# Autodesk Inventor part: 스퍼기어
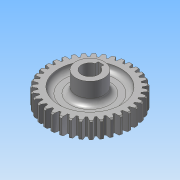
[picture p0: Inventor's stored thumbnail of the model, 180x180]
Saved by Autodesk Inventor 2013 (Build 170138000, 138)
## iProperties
Created: 2013-08
Part Number: 스퍼기어
Material: 강
Document SubType Name: Modeling
Designer: 한국산업디자인학원
Categories: <?xml version="1.0" encoding="UTF-16"?> <MemberInstance><Categories><FamilyTemplate><FamilyTemplateParameter ValueType="xs:double" Id="1" ObjectReferenceKey="da
Density: 1 g/cm^3
CustomPartVersion: 1
Author: 한국산업디자인학원
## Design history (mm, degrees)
sketch "Sketch1"
  geometry: C1 r 37 at (0, 0)
  constraints: 1 centre point
  dimensions: "d0" = 74 diameter of C1 (= da_da)
extrude "Extrusion1" new body sketch "Sketch1" distance "d1" = 15 (= da_b); taper "d2" = 0 deg
chamfer "모따기1" distance "d49" = 1; stored, may be unused: second distance "d50" = 2, angle "d51" = 45 deg
workplane "Work Plane2"
feature "피치 지름" dims "d4" = 10, "d5" = 0
workplane "Work Plane8"
workplane "Work Plane9"
feature "스퍼 기어" dims "da_b" = 15, "da_d" = 70, "da_aw" = 70, "da_da" = 74, "da_df" = 65, "da_dw" = 70, angle "da_beta" = 0 deg, "da_lefttooth" = 0, "da_righttooth" = 0
node "작업 평면11"
sketch "스케치3"
  geometry: L1 (-2.5, 7.071)-(-2.5, 9.8); L2 (-2.5, 9.8)-(2.5, 9.8); L3 (2.5, 9.8)-(2.5, 7.071); C1 r 12.5 at (0, 0); A1 r 7.5 centre (0, 0) between (-2.5, 7.071) and (2.5, 7.071); 1 further point
  constraints: 6 end point, 2 centre point, 2 coincident, 2 parallel, 2 point on circle, 1 perpendicular, 1 vertical
  dimensions: "d53" = 25 diameter of C1; "d55" = 15 diameter of A1; "d56" = 5 distance of L1.end L2.end; "d57" = 17.3 dimension on A1 L2
extrude "돌출2" join sketch "스케치3" distance "d58" = 31; taper "d59" = 0 deg
sketch "스케치4"
  geometry: L1 (2.5, 7.071)-(2.5, 9.8) reference; L2 (2.5, 9.8)-(-2.5, 9.8) reference; L3 (-2.5, 9.8)-(-2.5, 7.071) reference; A1 r 7.5 centre (0, 0) between (-2.5, 7.071) and (2.5, 7.071) reference; A2 r 7.5 centre (0, 0) between (-2.5, 7.071) and (2.5, 7.071) reference
extrude "돌출3" cut sketch "스케치3" stored distance "d60" = 31; taper "d61" = 0 deg
sketch "스케치5"
  geometry: C1 r 12.5 at (0, 0) reference; C2 r 27.5 at (0, 0); C3 r 12.5 at (0, 0) reference
  constraints: 1 centre point, 1 coincident
  dimensions: "d62" = 55 diameter of C2
extrude "돌출4" cut sketch "스케치5" distance "d64" = 5; taper "d65" = 0 deg
sketch "스케치6"
  geometry: C1 r 12.5 at (0, 0) reference; C2 r 27.5 at (0, 0) reference; C3 r 12.5 at (0, 0) reference
extrude "돌출5" cut sketch "스케치6" distance "d66" = 5; taper "d67" = 0 deg
fillet "모깎기1" dims "d68" = 5
sketch "스케치7"
  geometry: L1 (2.5, 7.071)-(2.5, 9.8) reference; L2 (2.5, 9.8)-(-2.5, 9.8) reference; L3 (-2.5, 9.8)-(-2.5, 7.071) reference; A1 r 7.5 centre (0, 0) between (2.5, 7.071) and (-2.5, 7.071) reference
extrude "돌출6" cut sketch "스케치7" stored distance "d69" = 5; taper "d70" = 0 deg
body "Solid1"
sketch "Sketch2"
  geometry: C1 r 37 at (0, 0) reference; C2 r 35 at (0, 0)
  constraints: 1 centre point, 1 coincident
  dimensions: "d3" = 70 diameter of C2 (= da_dw)
body "Srf1"
other parameters: "d17" = 0, "d34" = 0.8976 (computed from da_z), "d39" = 0, "d41" = 0, "d47" = 0, "d48" = 0, "d52" = 3
